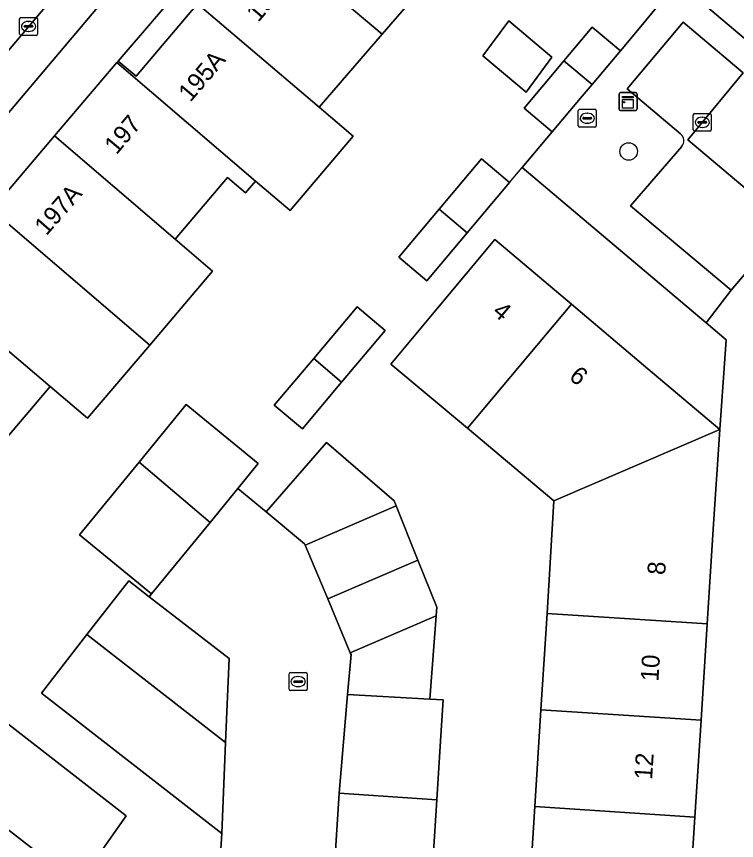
# Model space of a CAD drawing. Extents: x 160349 to 161355, y 381727 to 382854.
# Drawn here: x 160520.93 to 160561.12, y 382194.03 to 382240.01 of the extents above; entities that cross this region are included whole.
import ezdxf

# ---------------------------------------------------------------- set-up
doc = ezdxf.new("R2010")
doc.units = 0
for name, color, linetype in [('IMGEO_Boom', 7, 'Continuous'), ('IMGEO_Brandkraan', 7, 'Continuous'), ('IMGEO_Erf', 7, 'Continuous'), ('IMGEO_Kast', 7, 'Continuous'), ('IMGEO_Kolk', 7, 'Continuous'), ('IMGEO_Muur', 7, 'Continuous'), ('IMGEO_Pand', 7, 'Continuous'), ('IMGEO_Pand_nummerreeks', 7, 'Continuous'), ('IMGEO_Parkeervlak_open', 7, 'Continuous'), ('IMGEO_Rijbaan_lokaal_gesloten', 7, 'Continuous'), ('IMGEO_Rijbaan_lokaal_open', 7, 'Continuous'), ('IMGEO_Voetpad_open', 7, 'Continuous')]:
    doc.layers.add(name, color=color, linetype=linetype)

msp = doc.modelspace()

# ---------------------------------------------------------------- linework, layer by layer
at = {"layer": 'IMGEO_Boom'}
msp.add_circle((160555.103, 382232.482), 0.489, dxfattribs=at)
at = {"layer": 'IMGEO_Brandkraan'}
for p, q in [((160552.289, 382233.91), (160552.289, 382234.762)), ((160552.364, 382234.836), (160553.216, 382234.836)), ((160552.777, 382234.616), (160552.802, 382234.616)), ((160553.29, 382234.762), (160553.29, 382233.91)), ((160552.548, 382234.33), (160552.548, 382234.342)), ((160552.986, 382234.293), (160552.588, 382234.293)), ((160552.591, 382234.379), (160552.989, 382234.379)), ((160552.8, 382234.056), (160552.775, 382234.056)), ((160553.032, 382234.342), (160553.032, 382234.33)), ((160553.216, 382233.836), (160552.364, 382233.836))]:
    msp.add_line(p, q, dxfattribs=at)
for points in [[(160552.289, 382233.91), (160552.289, 382234.762)], [(160552.364, 382234.836), (160553.216, 382234.836)], [(160553.29, 382234.762), (160553.29, 382233.91)], [(160553.216, 382233.836), (160552.364, 382233.836)]]:
    msp.add_lwpolyline(points, dxfattribs=at)
for centre, radius, start, end in [((160552.366, 382234.76), 0.0765, 91.552, 178.448), ((160552.366, 382234.76), 0.0765, 91.552, 178.448), ((160553.214, 382234.76), 0.0765, 1.552, 88.448), ((160553.214, 382234.76), 0.0765, 1.552, 88.448), ((160552.588, 382234.339), 0.0403, 85.8775, 175.7526), ((160552.585, 382234.329), 0.0366, 178.938, 274.7102), ((160552.989, 382234.336), 0.043, 264.8664, 352.4533), ((160552.993, 382234.341), 0.0386, 1.7309, 96.639), ((160552.366, 382233.912), 0.0765, 181.552, 268.448), ((160552.366, 382233.912), 0.0765, 181.552, 268.448), ((160553.214, 382233.912), 0.0765, 271.552, 358.448), ((160553.214, 382233.912), 0.0765, 271.552, 358.448)]:
    msp.add_arc(centre, radius, start, end, dxfattribs=at)
for centre, major_axis, ratio, start_param, end_param in [((160552.776, 382234.336), (-0.387, 0.002), 0.722429, 4.712389, 7.853982), ((160552.801, 382234.336), (-0.39, 0.002), 0.717154, 1.570796, 4.712389)]:
    msp.add_ellipse(centre, major_axis=major_axis, ratio=ratio, start_param=start_param, end_param=end_param, dxfattribs=at)
at = {"layer": 'IMGEO_Erf'}
for points in [[(160537.301, 382250), (160526.611, 382237.529), (160527.605, 382236.685), (160531.029, 382240.717)], [(160544.869, 382243.113), (160541.347, 382239.029), (160537.826, 382234.945), (160539.732, 382233.327), (160536.214, 382229.184), (160534.277, 382230.829), (160533.717, 382230.18), (160532.715, 382231.032), (160529.784, 382227.581), (160531.88, 382225.797), (160528.373, 382221.678), (160524.894, 382217.59), (160522.807, 382219.367), (160519.076, 382214.973)], [(160549.523, 382190.617), (160549.861, 382195.931), (160550.202, 382201.314), (160550.544, 382206.698), (160550.93, 382212.991), (160546.1, 382217.031), (160541.818, 382220.612), (160544.424, 382223.737), (160547.626, 382227.576), (160551.91, 382223.955), (160556.178, 382220.348), (160560.18, 382216.966), (160560.539, 382221.977), (160559.424, 382222.918), (160549.153, 382231.581), (160550.831, 382233.579), (160549.262, 382234.899), (160550.939, 382236.893), (160551.485, 382237.543), (160553.067, 382239.424), (160554.636, 382238.104), (160555.404, 382239.017), (160556.93, 382240.845)], [(160532.234, 382191.813), (160532.401, 382194.416), (160522.323, 382202.243), (160524.865, 382205.516), (160527.201, 382208.522), (160528.348, 382207.631), (160528.478, 382207.798), (160524.452, 382211.093), (160527.772, 382215.149), (160530.399, 382218.358), (160534.425, 382215.062), (160533.287, 382213.672), (160534.868, 382212.377), (160538.239, 382216.238), (160542.016, 382212.987), (160542.13, 382212.704), (160543.335, 382209.68), (160544.386, 382207.043), (160544.351, 382206.565), (160544.006, 382201.913), (160544.751, 382201.869), (160544.587, 382199.299), (160544.396, 382196.3), (160544.193, 382193.099)], [(160519.508, 382201.256), (160527.055, 382195.395), (160524.379, 382191.584), (160516.472, 382197.725)]]:
    msp.add_lwpolyline(points, dxfattribs=at)
for points in [[(160546.966, 382237.82), (160548.404, 382239.778), (160550.811, 382237.753), (160549.374, 382235.794)], [(160546.885, 382232.07), (160548.454, 382230.75), (160546.085, 382227.932), (160543.84, 382225.262), (160542.271, 382226.582), (160544.522, 382229.259)], [(160539.942, 382223.811), (160541.511, 382222.491), (160539.081, 382219.6), (160536.891, 382216.995), (160535.322, 382218.315), (160537.525, 382220.936)]]:
    msp.add_lwpolyline(points, close=True, dxfattribs=at)
at = {"layer": 'IMGEO_Kast'}
for p, q in [((160554.565, 382234.841), (160554.565, 382235.682)), ((160554.565, 382235.682), (160554.565, 382234.841)), ((160554.64, 382235.766), (160555.481, 382235.766)), ((160555.481, 382235.766), (160554.64, 382235.766)), ((160555.565, 382235.691), (160555.565, 382234.85)), ((160555.565, 382234.85), (160555.565, 382235.691)), ((160555.49, 382234.766), (160554.649, 382234.766)), ((160554.649, 382234.766), (160555.49, 382234.766))]:
    msp.add_line(p, q, dxfattribs=at)
for points in [[(160554.76, 382235.556), (160555.36, 382235.556), (160555.36, 382235.471), (160554.76, 382235.471), (160554.76, 382235.556)], [(160554.76, 382235.381), (160555.36, 382235.381), (160555.36, 382234.892), (160554.76, 382234.892), (160554.76, 382235.381)]]:
    msp.add_lwpolyline(points, dxfattribs=at)
msp.add_circle((160554.844, 382235.23), 0.0377, dxfattribs=at)
for centre, start, end in [((160554.643, 382235.688), 92.4484, 184.2845), ((160554.643, 382235.688), 92.4484, 184.2845), ((160555.487, 382235.688), 2.4484, 94.2845), ((160555.487, 382235.688), 2.4484, 94.2845), ((160554.643, 382234.844), 182.4484, 274.2845), ((160554.643, 382234.844), 182.4484, 274.2845), ((160555.487, 382234.844), 272.4484, 4.2845), ((160555.487, 382234.844), 272.4484, 4.2845)]:
    msp.add_arc(centre, 0.0779, start, end, dxfattribs=at)
at = {"layer": 'IMGEO_Kolk'}
for p, q in [((160521.109, 382239.036), (160521.109, 382239.888)), ((160521.184, 382239.962), (160522.036, 382239.962)), ((160521.597, 382239.742), (160521.622, 382239.742)), ((160522.11, 382239.888), (160522.11, 382239.036)), ((160521.368, 382239.456), (160521.368, 382239.468)), ((160521.806, 382239.419), (160521.408, 382239.419)), ((160521.411, 382239.505), (160521.809, 382239.505)), ((160521.62, 382239.182), (160521.595, 382239.182)), ((160521.852, 382239.468), (160521.852, 382239.456)), ((160522.036, 382238.962), (160521.184, 382238.962)), ((160558.708, 382233.681), (160558.708, 382234.533)), ((160558.783, 382234.607), (160559.635, 382234.607)), ((160559.709, 382234.533), (160559.709, 382233.681)), ((160558.967, 382234.101), (160558.967, 382234.113)), ((160559.405, 382234.064), (160559.007, 382234.064)), ((160559.01, 382234.15), (160559.408, 382234.15)), ((160559.196, 382234.387), (160559.221, 382234.387)), ((160559.451, 382234.113), (160559.451, 382234.101)), ((160559.635, 382233.607), (160558.783, 382233.607)), ((160559.219, 382233.827), (160559.194, 382233.827)), ((160536.15, 382202.469), (160536.15, 382203.321)), ((160536.225, 382203.395), (160537.077, 382203.395)), ((160537.151, 382203.321), (160537.151, 382202.469)), ((160536.409, 382202.889), (160536.409, 382202.901)), ((160536.847, 382202.852), (160536.449, 382202.852)), ((160536.452, 382202.938), (160536.85, 382202.938)), ((160536.638, 382203.175), (160536.663, 382203.175)), ((160536.893, 382202.901), (160536.893, 382202.889)), ((160537.077, 382202.395), (160536.225, 382202.395)), ((160536.661, 382202.615), (160536.636, 382202.615))]:
    msp.add_line(p, q, dxfattribs=at)
for points in [[(160521.109, 382239.036), (160521.109, 382239.888)], [(160521.184, 382239.962), (160522.036, 382239.962)], [(160522.11, 382239.888), (160522.11, 382239.036)], [(160522.036, 382238.962), (160521.184, 382238.962)], [(160558.708, 382233.681), (160558.708, 382234.533)], [(160558.783, 382234.607), (160559.635, 382234.607)], [(160559.709, 382234.533), (160559.709, 382233.681)], [(160559.635, 382233.607), (160558.783, 382233.607)], [(160536.15, 382202.469), (160536.15, 382203.321)], [(160536.225, 382203.395), (160537.077, 382203.395)], [(160537.151, 382203.321), (160537.151, 382202.469)], [(160537.077, 382202.395), (160536.225, 382202.395)]]:
    msp.add_lwpolyline(points, dxfattribs=at)
for centre, radius, start, end in [((160521.186, 382239.886), 0.0765, 91.552, 178.448), ((160521.186, 382239.886), 0.0765, 91.552, 178.448), ((160522.034, 382239.886), 0.0765, 1.552, 88.448), ((160522.034, 382239.886), 0.0765, 1.552, 88.448), ((160521.408, 382239.465), 0.0403, 85.8775, 175.7526), ((160521.405, 382239.455), 0.0366, 178.938, 274.7102), ((160521.809, 382239.462), 0.043, 264.8664, 352.4533), ((160521.813, 382239.467), 0.0386, 1.7309, 96.639), ((160521.186, 382239.038), 0.0765, 181.552, 268.448), ((160521.186, 382239.038), 0.0765, 181.552, 268.448), ((160522.034, 382239.038), 0.0765, 271.552, 358.448), ((160522.034, 382239.038), 0.0765, 271.552, 358.448), ((160558.785, 382234.531), 0.0765, 91.552, 178.448), ((160558.785, 382234.531), 0.0765, 91.552, 178.448), ((160559.633, 382234.531), 0.0765, 1.552, 88.448), ((160559.633, 382234.531), 0.0765, 1.552, 88.448), ((160559.007, 382234.11), 0.0403, 85.8775, 175.7526), ((160559.004, 382234.1), 0.0366, 178.938, 274.7102), ((160559.408, 382234.107), 0.043, 264.8664, 352.4533), ((160559.412, 382234.112), 0.0386, 1.7309, 96.639), ((160558.785, 382233.683), 0.0765, 181.552, 268.448), ((160558.785, 382233.683), 0.0765, 181.552, 268.448), ((160559.633, 382233.683), 0.0765, 271.552, 358.448), ((160559.633, 382233.683), 0.0765, 271.552, 358.448), ((160536.227, 382203.319), 0.0765, 91.552, 178.448), ((160536.227, 382203.319), 0.0765, 91.552, 178.448), ((160537.075, 382203.319), 0.0765, 1.552, 88.448), ((160537.075, 382203.319), 0.0765, 1.552, 88.448), ((160536.449, 382202.898), 0.0403, 85.8775, 175.7526), ((160536.446, 382202.888), 0.0366, 178.938, 274.7102), ((160536.85, 382202.895), 0.043, 264.8664, 352.4533), ((160536.854, 382202.9), 0.0386, 1.7309, 96.639), ((160536.227, 382202.471), 0.0765, 181.552, 268.448), ((160536.227, 382202.471), 0.0765, 181.552, 268.448), ((160537.075, 382202.471), 0.0765, 271.552, 358.448), ((160537.075, 382202.471), 0.0765, 271.552, 358.448)]:
    msp.add_arc(centre, radius, start, end, dxfattribs=at)
for centre, major_axis, ratio, start_param, end_param in [((160521.596, 382239.462), (-0.387, 0.002), 0.722429, 4.712389, 7.853982), ((160521.621, 382239.462), (-0.39, 0.002), 0.717154, 1.570796, 4.712389), ((160559.195, 382234.107), (-0.387, 0.002), 0.722429, 4.712389, 7.853982), ((160559.22, 382234.107), (-0.39, 0.002), 0.717154, 1.570796, 4.712389), ((160536.637, 382202.895), (-0.387, 0.002), 0.722429, 4.712389, 7.853982), ((160536.662, 382202.895), (-0.39, 0.002), 0.717154, 1.570796, 4.712389)]:
    msp.add_ellipse(centre, major_axis=major_axis, ratio=ratio, start_param=start_param, end_param=end_param, dxfattribs=at)
at = {"layer": 'IMGEO_Muur'}
for points in [[(160548.642, 382247.847), (160556.93, 382240.845), (160555.404, 382239.017)], [(160549.153, 382231.581), (160552.508, 382235.573)], [(160548.454, 382230.75), (160549.153, 382231.581)]]:
    msp.add_lwpolyline(points, dxfattribs=at)
at = {"layer": 'IMGEO_Pand'}
for points in [[(160537.987, 382248.909), (160534.5, 382244.803), (160541.347, 382239.029), (160544.869, 382243.113)], [(160541.347, 382239.029), (160534.5, 382244.803), (160531.029, 382240.717), (160537.826, 382234.945)], [(160537.826, 382234.945), (160531.029, 382240.717), (160527.605, 382236.685), (160526.611, 382237.529), (160526.535, 382237.44), (160534.277, 382230.829), (160536.214, 382229.184), (160539.732, 382233.327)], [(160546.966, 382237.82), (160549.374, 382235.794), (160550.811, 382237.753), (160548.404, 382239.778)], [(160553.067, 382239.424), (160551.485, 382237.543), (160553.054, 382236.222), (160554.636, 382238.104)], [(160523.058, 382233.355), (160529.784, 382227.581), (160532.715, 382231.032), (160533.717, 382230.18), (160534.277, 382230.829), (160526.535, 382237.44)], [(160553.054, 382236.222), (160551.485, 382237.543), (160550.939, 382236.893), (160549.262, 382234.899), (160550.831, 382233.579), (160552.508, 382235.573)], [(160523.058, 382233.355), (160519.539, 382229.221), (160528.373, 382221.678), (160531.88, 382225.797), (160529.784, 382227.581)], [(160544.522, 382229.259), (160546.085, 382227.932), (160548.454, 382230.75), (160546.885, 382232.07)], [(160519.539, 382229.221), (160516.043, 382225.114), (160522.807, 382219.367), (160524.894, 382217.59), (160528.373, 382221.678)], [(160544.522, 382229.259), (160542.271, 382226.582), (160543.84, 382225.262), (160546.085, 382227.932)], [(160546.1, 382217.031), (160551.91, 382223.955), (160547.626, 382227.576), (160544.424, 382223.737), (160541.818, 382220.612)], [(160522.807, 382219.367), (160516.043, 382225.114), (160512.124, 382220.51), (160512.016, 382220.381), (160519.076, 382214.973)], [(160546.1, 382217.031), (160550.93, 382212.991), (160560.18, 382216.966), (160556.178, 382220.348), (160551.91, 382223.955)], [(160537.525, 382220.936), (160539.081, 382219.6), (160541.511, 382222.491), (160539.942, 382223.811)], [(160537.525, 382220.936), (160535.322, 382218.315), (160536.891, 382216.995), (160539.081, 382219.6)], [(160530.399, 382218.358), (160527.772, 382215.149), (160531.737, 382211.779), (160533.287, 382213.672), (160534.425, 382215.062)], [(160550.544, 382206.698), (160559.488, 382206.127), (160559.842, 382211.675), (160560.18, 382216.966), (160550.93, 382212.991)], [(160537.044, 382210.517), (160542.13, 382212.704), (160542.016, 382212.987), (160538.239, 382216.238), (160534.868, 382212.377), (160537.015, 382210.587)], [(160527.772, 382215.149), (160524.452, 382211.093), (160528.478, 382207.798), (160531.737, 382211.779)], [(160538.303, 382207.517), (160543.335, 382209.68), (160542.13, 382212.704), (160537.044, 382210.517)], [(160544.351, 382206.565), (160544.386, 382207.043), (160543.335, 382209.68), (160538.303, 382207.517), (160539.565, 382204.508)], [(160532.796, 382204.176), (160528.348, 382207.631), (160527.201, 382208.522), (160524.865, 382205.516), (160532.607, 382199.503)], [(160544.351, 382206.565), (160539.565, 382204.508), (160539.606, 382204.411), (160539.407, 382202.182), (160544.006, 382201.913)], [(160550.544, 382206.698), (160550.202, 382201.314), (160559.144, 382200.737), (160559.488, 382206.127)], [(160524.865, 382205.516), (160522.323, 382202.243), (160532.401, 382194.416), (160532.607, 382199.503)], [(160544.587, 382199.299), (160544.751, 382201.869), (160544.006, 382201.913), (160539.407, 382202.182), (160538.935, 382196.669), (160544.396, 382196.3)], [(160519.508, 382201.256), (160519.148, 382201.536), (160518.871, 382201.143), (160518.49, 382200.599), (160517.774, 382199.579), (160516.472, 382197.725), (160524.379, 382191.584), (160527.055, 382195.395)], [(160550.202, 382201.314), (160549.861, 382195.931), (160558.799, 382195.327), (160559.144, 382200.737)], [(160544.396, 382196.3), (160538.935, 382196.669), (160538.73, 382193.446), (160544.193, 382193.099)], [(160558.799, 382195.327), (160549.861, 382195.931), (160549.523, 382190.617), (160549.505, 382190.329), (160553.455, 382190.077), (160558.444, 382189.759)]]:
    msp.add_lwpolyline(points, close=True, dxfattribs=at)
at = {"layer": 'IMGEO_Parkeervlak_open'}
msp.add_lwpolyline([(160528.591, 382244.246), (160533.45, 382250.04), (160531.752, 382251.474), (160526.868, 382245.691), (160511.347, 382227.324), (160513.09, 382225.901)], close=True, dxfattribs=at)
msp.add_lwpolyline([(160558.058, 382232.762), (160555.205, 382229.439), (160560.815, 382224.738), (160563.969, 382228.451), (160558.4, 382233.13), (160561.493, 382236.875), (160558.133, 382239.693), (160555.012, 382235.986), (160558.001, 382233.464)], dxfattribs=at)
msp.add_arc((160557.682, 382233.085), 0.495, 319.3304, 49.9536, dxfattribs=at)
at = {"layer": 'IMGEO_Rijbaan_lokaal_gesloten'}
msp.add_lwpolyline([(160491.474, 382203.794), (160492.28, 382204.751), (160493.513, 382206.216), (160494.473, 382207.357), (160510.031, 382225.769), (160511.347, 382227.324), (160526.868, 382245.691), (160531.752, 382251.474), (160534.997, 382255.317), (160543.539, 382265.412), (160545.439, 382267.658), (160549.933, 382272.986), (160548.551, 382274.127), (160544.163, 382268.947), (160491.199, 382206.25)], dxfattribs=at)
at = {"layer": 'IMGEO_Rijbaan_lokaal_open'}
for points in [[(160567.189, 382239.935), (160564.871, 382241.937), (160560.156, 382245.921), (160553.337, 382251.819), (160546.421, 382257.67), (160545.617, 382258.378), (160542.577, 382254.762), (160543.44, 382254.08), (160551.105, 382247.654), (160555.02, 382244.323), (160562.487, 382238.003)], [(160561.493, 382236.875), (160558.4, 382233.13), (160563.969, 382228.451), (160564.097, 382228.603)], [(160538.73, 382193.446), (160538.935, 382196.669), (160539.407, 382202.182), (160539.606, 382204.411), (160539.565, 382204.508), (160538.303, 382207.517), (160537.044, 382210.517), (160537.015, 382210.587), (160534.868, 382212.377), (160533.287, 382213.672), (160531.737, 382211.779), (160528.478, 382207.798), (160528.348, 382207.631), (160532.796, 382204.176), (160532.607, 382199.503), (160532.401, 382194.416), (160532.234, 382191.813)]]:
    msp.add_lwpolyline(points, dxfattribs=at)
at = {"layer": 'IMGEO_Voetpad_open'}
for points in [[(160493.42, 382200.205), (160494.676, 382201.531), (160497.92, 382204.921), (160500, 382207.094), (160501.458, 382208.617), (160506.834, 382214.235), (160507.36, 382214.859), (160512.016, 382220.381), (160512.124, 382220.51), (160516.043, 382225.114), (160519.539, 382229.221), (160523.058, 382233.355), (160526.535, 382237.44), (160526.611, 382237.529), (160537.301, 382250), (160540.994, 382254.308), (160541.876, 382255.34), (160541.655, 382255.523)], [(160543.44, 382254.08), (160542.577, 382254.762), (160541.876, 382255.34), (160540.994, 382254.308), (160546.093, 382250), (160548.642, 382247.847), (160556.93, 382240.845), (160555.404, 382239.017), (160554.636, 382238.104), (160553.054, 382236.222), (160552.508, 382235.573), (160550.831, 382233.579), (160549.153, 382231.581), (160559.424, 382222.918), (160560.815, 382224.738), (160555.205, 382229.439), (160558.058, 382232.762)], [(160562.487, 382238.003), (160555.02, 382244.323), (160551.105, 382247.654), (160543.44, 382254.08)], [(160528.591, 382244.246), (160513.09, 382225.901), (160511.347, 382227.324), (160510.031, 382225.769), (160511.73, 382224.274), (160496.117, 382205.994), (160494.473, 382207.357), (160493.513, 382206.216), (160495.22, 382204.761), (160492.685, 382201.786), (160488.98, 382197.683), (160483.694, 382192.318), (160478.584, 382187.303)], [(160558.001, 382233.464), (160555.012, 382235.986), (160558.133, 382239.693), (160561.493, 382236.875)], [(160564.097, 382228.603), (160563.969, 382228.451), (160560.815, 382224.738), (160559.424, 382222.918), (160560.539, 382221.977), (160560.18, 382216.966), (160559.842, 382211.675), (160559.488, 382206.127), (160559.144, 382200.737), (160558.799, 382195.327), (160558.444, 382189.759), (160558.16, 382184.17), (160557.795, 382178.692), (160557.436, 382173.292), (160557.078, 382167.913), (160556.719, 382162.524), (160556.36, 382157.135), (160556.002, 382151.755), (160555.629, 382146.146), (160555.458, 382143.576), (160556.874, 382143.486), (160556.542, 382138.8), (160556.158, 382134.351)]]:
    msp.add_lwpolyline(points, dxfattribs=at)
msp.add_arc((160557.682, 382233.085), 0.495, 319.3304, 49.9536, dxfattribs=at)

# ---------------------------------------------------------------- texts
at = {"layer": 'IMGEO_Pand_nummerreeks'}
for s, rotation, p in [('195', 49.6573, (160534.432, 382239.656)), ('195A', 49.6573, (160530.641, 382235.193)), ('197', 49.8389, (160526.516, 382232.261)), ('197A', 48.8689, (160522.6, 382227.74)), ('4', 319.7961, (160547.437, 382223.442)), ('6', 319.7961, (160551.713, 382219.828)), ('8', 86.3501, (160557.135, 382208.825)), ('10', 86.3501, (160556.757, 382202.886)), ('12', 86.3501, (160556.406, 382197.401))]:
    msp.add_text(s, height=1, rotation=rotation, dxfattribs=at).set_placement(p)

doc.saveas('drawing.dxf')
